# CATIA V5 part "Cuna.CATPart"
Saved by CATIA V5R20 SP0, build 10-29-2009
Part number: Cuña
Bounding box of the stored display mesh (mm): x -20 to 20, y 0 to 25, z 0 to 80
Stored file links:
  C:\Users\Ricardo\Desktop\Nueva carpeta (3)\Cuna.CATPart
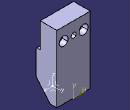
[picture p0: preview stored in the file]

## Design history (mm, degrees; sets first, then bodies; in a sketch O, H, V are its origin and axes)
AxisSystem1: origin (0, 0, 0), X (1, 0, 0), Y (0, 1, 0), Z (0, 0, 1)
Body1 (main body)
  Sketch1 on YZ plane of AxisSystem1, origin (0, 0, 0), H (0, 1, 0), V (0, 0, 1)
    line L1 (0, 80) -> (25, 80)
    line L2 (25, 80) -> (25, 0)
    line L3 (25, 0) -> (0, 0)
    line L4 (0, 0) -> (0, 80)
    point P4 (0, 0)
    length L1 = 25
    length L2 = 80
    horizontal: L1 H, L3 H
    vertical: L2 V, L4 V
    coincidence: O P4
  Pad1: profile Sketch1, direction (1, 0, 0), length 20, mirrored extent
  Sketch2 on end face of Pad1, origin (20, 0, 0), H (0, 1, 0), V (0, 0, 1)
    line L1 (0, 0) -> (0, 20)
    point P1 (0, 0)
    line L2 (0, 20) -> (16.782, 0)
    point P3 (16.782, 0)
    line L3 (0, 0) -> (16.782, 0)
    length L1 = 20
    angle L2 H = 50
    vertical: L1 V
    coincidence: P1 O, P3 H
    horizontal: L3 H
  Pocket1: profile Sketch2, direction (-1, 0, 0), length 40
  Sketch3 on end face of Pad1, origin (20, 0, 0), H (0, 1, 0), V (0, 0, 1)
    point P1 (0, 80)
    line L1 (0, 80) -> (5, 80)
    line L2 (5, 80) -> (5, 50)
    line L3 (5, 50) -> (0, 50)
    line L4 (0, 50) -> (0, 80)
    reference projected point E1 (0, 80) from vertex [face of Pad1 from Sketch1.L1 | end face of Pad1 | face of Pad1 from Sketch1.L4]
    length L1 = 5
    length L2 = 30
    horizontal: L1 H, L3 H
    vertical: L2 V, L4 V
    coincidence: P1 E1
  Pocket2: profile Sketch3, direction (-1, 0, 0), length 40
  Chamfer1: length 1, angle 45, on edge [face of Pocket2 from Sketch3.L3 | face of Pad1 from Sketch1.L4]
  Sketch4 on face of Pad1 from Sketch1.L2, origin (-15, 25, 65), H (1, 0, 0), V (0, 0, -1)
    point P1 (3, 0)
    reference projected point E1 (3, 0) from Sketch7.P1
    coincidence: E1 P1
  Hole1: placed by Sketch4, at (-12, 25, 65) direction (0, -1, 0), diameter 7, depth 20, counterbore diameter 11, counterbore depth 6.6
  RectPattern1: of Hole1, direction 1 instances 2, spacing 24, along edge [face of Pad1 from Sketch1.L1 | face of Pocket2 from Sketch3.L2] reversed
  Sketch5 on face of Pad1 from Sketch1.L2, origin (0, 25, 65), H (1, 0, 0), V (0, 0, -1)
    point P1 (0, 0)
    reference projected point E1 (0, 0) from Sketch6.P1
    coincidence: E1 P1
  Hole2: placed by Sketch5, at (0, 25, 65) direction (0, -1, 0), diameter 6, depth 20
  Sketch6 on face of Pad1 from Sketch1.L2, origin (0, 25, 0), H (-1, 0, 0), V (0, 0, 1)
    point P1 (0, 65)
    reference projected line E1 (20, 80) -> (-20, 80) from edge [face of Pad1 from Sketch1.L1 | face of Pad1 from Sketch1.L2]
    distance E1 P1 = 15
    coincidence: P1 V
  Sketch7 on face of Pad1 from Sketch1.L2, origin (0, 25, 0), H (-1, 0, 0), V (0, 0, 1)
    point P1 (12, 65)
    reference projected line E1 (20, 80) -> (-20, 80) from edge [face of Pad1 from Sketch1.L1 | face of Pad1 from Sketch1.L2]
    reference projected line E2 (20, 0) -> (20, 80) from edge [start face of Pad1 | face of Pad1 from Sketch1.L2]
    distance P1 E1 = 15
    distance P1 E2 = 8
